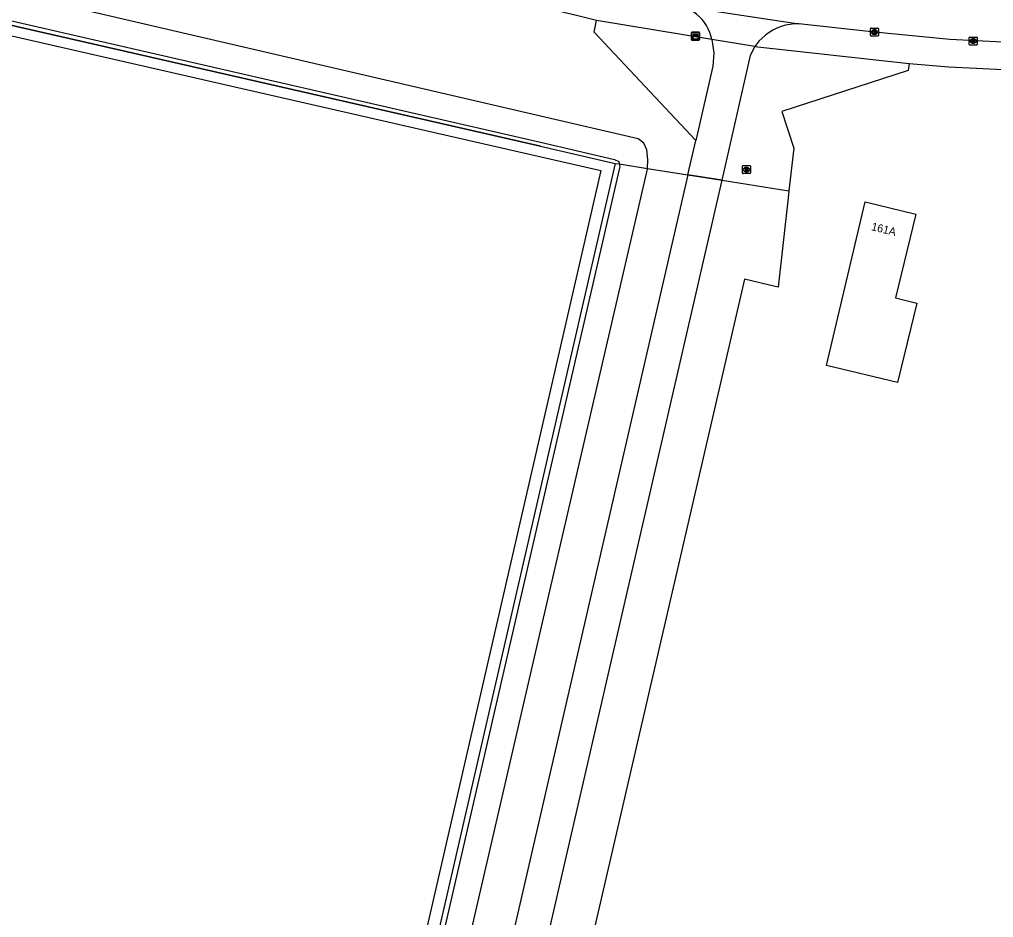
# Model space of a CAD drawing. Extents: x 160203 to 161526, y 379529 to 381797.
# Drawn here: x 160934.9 to 161056.6, y 381615.5 to 381727.7 of the extents above; entities that cross this region are included whole.
import ezdxf

# ---------------------------------------------------------------- set-up
doc = ezdxf.new("R2010")
doc.units = 0
for name, color, linetype in [('IMGEO_Fietspad_gesloten', 7, 'Continuous'), ('IMGEO_Groenvoorziening', 7, 'Continuous'), ('IMGEO_Hek', 7, 'Continuous'), ('IMGEO_Kast', 7, 'Continuous'), ('IMGEO_Kolk', 7, 'Continuous'), ('IMGEO_Loofbos', 7, 'Continuous'), ('IMGEO_Pand', 7, 'Continuous'), ('IMGEO_Pand_nummerreeks', 7, 'Continuous'), ('IMGEO_Rijbaan_lokaal_gesloten', 7, 'Continuous'), ('IMGEO_Rijbaan_lokaal_open', 7, 'Continuous'), ('IMGEO_Rioolput', 7, 'Continuous'), ('IMGEO_Voetpad_open', 7, 'Continuous'), ('IMGEO_Waterloop', 7, 'Continuous')]:
    doc.layers.add(name, color=color, linetype=linetype)

msp = doc.modelspace()

# ---------------------------------------------------------------- linework, layer by layer
at = {"layer": 'IMGEO_Fietspad_gesloten'}
msp.add_lwpolyline([(161059.6, 381724.82), (161059.22, 381724.83), (161057.74, 381724.86), (161051.18, 381725.22), (161049.02, 381725.4), (161041.76, 381726.12), (161032.31, 381727.14)], dxfattribs=at)
at = {"layer": 'IMGEO_Groenvoorziening'}
for points in [[(160905.47, 381607.79), (160932.99, 381725.88), (161007.56, 381708.83), (160982.28, 381598.99), (160979.33, 381590.62)], [(161046.1, 381722.18), (161045.95, 381721.32), (161030.18, 381716.2), (161031.67, 381711.63), (161031.06, 381706.3)], [(161022.69, 381707.62), (161031.06, 381706.3)], [(161031.06, 381706.3), (161030.96, 381705.4), (161029.69, 381694.26), (161028.46, 381694.55), (161025.49, 381695.25), (161006.56, 381613.31), (161001.18, 381614.12)]]:
    msp.add_lwpolyline(points, dxfattribs=at)
at = {"layer": 'IMGEO_Hek'}
for points in [[(161000, 381711.85), (160931.91, 381727.39)], [(161000, 381711.85), (161009.35, 381709.72)], [(161009.35, 381709.72), (161000, 381669.16)], [(161009.35, 381709.72), (161009.85, 381709.64)], [(161009.85, 381709.64), (161013.36, 381709.08)], [(161013.36, 381709.08), (161018.41, 381708.29)], [(161018.41, 381708.29), (161022.69, 381707.62)], [(161022.69, 381707.62), (161031.06, 381706.3)], [(161000, 381669.16), (160982.41, 381592.73), (160991.3, 381590.54)]]:
    msp.add_lwpolyline(points, dxfattribs=at)
at = {"layer": 'IMGEO_Kast'}
for p, q in [((161018.95, 381726.11), (161019.79, 381726.11)), ((161019.79, 381726.11), (161018.95, 381726.11)), ((161018.87, 381725.18), (161018.87, 381726.02)), ((161018.87, 381726.02), (161018.87, 381725.18)), ((161019.8, 381725.11), (161018.96, 381725.11)), ((161018.96, 381725.11), (161019.8, 381725.11)), ((161019.87, 381726.03), (161019.87, 381725.19)), ((161019.87, 381725.19), (161019.87, 381726.03))]:
    msp.add_line(p, q, dxfattribs=at)
for points in [[(161019.07, 381725.9), (161019.67, 381725.9), (161019.67, 381725.81), (161019.07, 381725.81), (161019.07, 381725.9)], [(161019.07, 381725.72), (161019.67, 381725.72), (161019.67, 381725.24), (161019.07, 381725.24), (161019.07, 381725.72)]]:
    msp.add_lwpolyline(points, dxfattribs=at)
msp.add_circle((161019.15, 381725.57), 0.0377, dxfattribs=at)
for centre, start, end in [((161018.95, 381726.03), 92.4484, 184.2845), ((161018.95, 381726.03), 92.4484, 184.2845), ((161019.79, 381726.03), 2.4484, 94.2845), ((161019.79, 381726.03), 2.4484, 94.2845), ((161018.95, 381725.19), 182.4484, 274.2845), ((161018.95, 381725.19), 182.4484, 274.2845), ((161019.79, 381725.19), 272.4484, 4.2845), ((161019.79, 381725.19), 272.4484, 4.2845)]:
    msp.add_arc(centre, 0.0779, start, end, dxfattribs=at)
at = {"layer": 'IMGEO_Kolk'}
for p, q in [((161041.24, 381725.69), (161041.24, 381726.55)), ((161041.32, 381726.62), (161042.17, 381726.62)), ((161041.73, 381726.4), (161041.75, 381726.4)), ((161042.24, 381726.55), (161042.24, 381725.69)), ((161042.17, 381725.62), (161041.32, 381725.62)), ((161041.75, 381725.84), (161041.73, 381725.84)), ((161053.6, 381724.58), (161053.6, 381725.44)), ((161053.67, 381725.51), (161054.52, 381725.51)), ((161054.08, 381725.29), (161054.11, 381725.29)), ((161054.6, 381725.44), (161054.6, 381724.58)), ((161054.52, 381724.51), (161053.67, 381724.51)), ((161054.11, 381724.73), (161054.08, 381724.73))]:
    msp.add_line(p, q, dxfattribs=at)
for points in [[(161041.24, 381725.69), (161041.24, 381726.55)], [(161041.32, 381726.62), (161042.17, 381726.62)], [(161041.56, 381726.32), (161041.69, 381726.32), (161041.69, 381726.17), (161041.81, 381726.32), (161041.98, 381726.32), (161041.83, 381726.17), (161041.99, 381725.92), (161041.83, 381725.92), (161041.75, 381726.09), (161041.69, 381726.02), (161041.69, 381725.92), (161041.56, 381725.92), (161041.56, 381726.32)], [(161042.24, 381726.55), (161042.24, 381725.69)], [(161042.17, 381725.62), (161041.32, 381725.62)], [(161053.6, 381724.58), (161053.6, 381725.44)], [(161053.67, 381725.51), (161054.52, 381725.51)], [(161053.92, 381725.21), (161054.04, 381725.21), (161054.04, 381725.06), (161054.17, 381725.21), (161054.33, 381725.21), (161054.19, 381725.06), (161054.34, 381724.81), (161054.19, 381724.81), (161054.1, 381724.98), (161054.04, 381724.91), (161054.04, 381724.81), (161053.92, 381724.81), (161053.92, 381725.21)], [(161054.6, 381725.44), (161054.6, 381724.58)], [(161054.52, 381724.51), (161053.67, 381724.51)]]:
    msp.add_lwpolyline(points, dxfattribs=at)
for centre, start, end in [((161041.32, 381726.55), 91.552, 178.448), ((161041.32, 381726.55), 91.552, 178.448), ((161042.17, 381726.55), 1.552, 88.448), ((161042.17, 381726.55), 1.552, 88.448), ((161041.32, 381725.7), 181.552, 268.448), ((161041.32, 381725.7), 181.552, 268.448), ((161042.17, 381725.7), 271.552, 358.448), ((161042.17, 381725.7), 271.552, 358.448), ((161053.67, 381725.44), 91.552, 178.448), ((161053.67, 381725.44), 91.552, 178.448), ((161054.52, 381725.44), 1.552, 88.448), ((161054.52, 381725.44), 1.552, 88.448), ((161053.67, 381724.59), 181.552, 268.448), ((161053.67, 381724.59), 181.552, 268.448), ((161054.52, 381724.59), 271.552, 358.448), ((161054.52, 381724.59), 271.552, 358.448)]:
    msp.add_arc(centre, 0.0765, start, end, dxfattribs=at)
for centre, major_axis, ratio, start_param, end_param in [((161041.73, 381726.12), (-0.387, 0.002), 0.722429, 4.712389, 7.853982), ((161041.75, 381726.12), (-0.39, 0.002), 0.717154, 1.570796, 4.712389), ((161054.08, 381725.01), (-0.387, 0.002), 0.722429, 4.712389, 7.853982), ((161054.11, 381725.01), (-0.39, 0.002), 0.717154, 1.570796, 4.712389)]:
    msp.add_ellipse(centre, major_axis=major_axis, ratio=ratio, start_param=start_param, end_param=end_param, dxfattribs=at)
at = {"layer": 'IMGEO_Loofbos'}
for points in [[(160885.25, 381510.67), (160899.54, 381573.29), (160879.8, 381577.74), (160888.45, 381614.64), (160904.95, 381610.88), (160911.88, 381640.18), (160931.91, 381727.39), (161000, 381711.85), (161009.35, 381709.72)], [(161019.4, 381712.56), (161006.69, 381726.12), (161006.98, 381727.59)], [(161009.35, 381709.72), (161000, 381669.16), (160982.41, 381592.73), (160991.3, 381590.54)], [(161009.35, 381709.72), (161009.85, 381709.64)], [(161013.36, 381709.08), (161018.41, 381708.29)]]:
    msp.add_lwpolyline(points, dxfattribs=at)
at = {"layer": 'IMGEO_Pand'}
msp.add_lwpolyline([(161044.63, 381682.32), (161035.76, 381684.47), (161040.57, 381704.93), (161046.74, 381703.43), (161046.9, 381703.39), (161044.36, 381692.91), (161047.04, 381692.26), (161044.63, 381682.32)], dxfattribs=at)
at = {"layer": 'IMGEO_Rijbaan_lokaal_gesloten'}
for points in [[(161021.4, 381725.18), (161021.68, 381723.53), (161021.55, 381721.86), (161019.4, 381712.56)], [(161026.81, 381724.32), (161021.4, 381725.18)], [(161022.69, 381707.62), (161026.27, 381723.21), (161026.81, 381724.32)], [(161018.41, 381708.29), (161019.4, 381712.56)], [(161018.41, 381708.29), (161000, 381628.33), (160991.3, 381590.54)], [(161022.69, 381707.62), (161018.41, 381708.29)], [(161001.18, 381614.12), (161022.69, 381707.62)]]:
    msp.add_lwpolyline(points, dxfattribs=at)
at = {"layer": 'IMGEO_Rijbaan_lokaal_open'}
for points in [[(161017.12, 381729.45), (161032.31, 381727.14)], [(161021.4, 381725.18), (161021.3, 381725.64), (161021.15, 381726.09), (161020.97, 381726.53), (161020.74, 381726.94), (161020.49, 381727.34), (161020.19, 381727.71), (161019.87, 381728.05), (161019.51, 381728.36), (161019.13, 381728.64), (161018.73, 381728.89), (161018.3, 381729.09), (161017.86, 381729.26), (161017.4, 381729.39), (161017.12, 381729.45)], [(161032.31, 381727.14), (161031.75, 381727.14), (161031.19, 381727.09), (161030.63, 381726.98), (161030.09, 381726.83), (161029.56, 381726.63), (161029.06, 381726.38), (161028.58, 381726.09), (161028.12, 381725.76), (161027.7, 381725.38), (161027.31, 381724.98), (161026.96, 381724.53), (161026.81, 381724.32)]]:
    msp.add_lwpolyline(points, dxfattribs=at)
at = {"layer": 'IMGEO_Rioolput'}
for p, q in [((161025.25, 381708.52), (161025.25, 381709.37)), ((161025.32, 381709.44), (161026.18, 381709.44)), ((161025.74, 381709.22), (161025.76, 381709.22)), ((161026.25, 381709.37), (161026.25, 381708.52)), ((161026.18, 381708.44), (161025.32, 381708.44)), ((161025.76, 381708.66), (161025.73, 381708.66))]:
    msp.add_line(p, q, dxfattribs=at)
for points in [[(161025.25, 381708.52), (161025.25, 381709.37)], [(161025.32, 381709.44), (161026.18, 381709.44)], [(161025.84, 381709.14), (161025.58, 381709.14), (161025.58, 381708.74)], [(161025.76, 381709.06), (161025.71, 381709.06), (161025.71, 381708.98)], [(161026.25, 381709.37), (161026.25, 381708.52)], [(161026.18, 381708.44), (161025.32, 381708.44)], [(161025.58, 381708.74), (161025.71, 381708.74), (161025.71, 381708.9), (161025.72, 381708.9)], [(161025.71, 381708.98), (161025.76, 381708.98)], [(161025.77, 381708.87), (161025.84, 381708.74), (161025.98, 381708.74), (161025.91, 381708.87)]]:
    msp.add_lwpolyline(points, dxfattribs=at)
for centre, radius, start, end in [((161025.32, 381709.37), 0.0765, 91.552, 178.448), ((161025.32, 381709.37), 0.0765, 91.552, 178.448), ((161025.77, 381708.96), 0.0964, 77.0061, 93.1865), ((161025.78, 381709.02), 0.0378, 276.6634, 79.6772), ((161025.84, 381709.03), 0.109, 350.3612, 89.416), ((161026.17, 381709.37), 0.0765, 1.552, 88.448), ((161026.17, 381709.37), 0.0765, 1.552, 88.448), ((161025.32, 381708.52), 0.0765, 181.552, 268.448), ((161025.32, 381708.52), 0.0765, 181.552, 268.448), ((161025.72, 381708.85), 0.0533, 26.0293, 88.6989), ((161025.75, 381709.17), 0.19, 274.7715, 282.9687), ((161025.83, 381709.03), 0.112, 277.5842, 350.9817), ((161025.82, 381708.81), 0.108, 29.5134, 73.7905), ((161026.17, 381708.52), 0.0765, 271.552, 358.448), ((161026.17, 381708.52), 0.0765, 271.552, 358.448)]:
    msp.add_arc(centre, radius, start, end, dxfattribs=at)
for centre, major_axis, ratio, start_param, end_param in [((161025.74, 381708.94), (-0.387, 0.002), 0.722429, 4.712389, 7.853982), ((161025.76, 381708.94), (-0.39, 0.002), 0.717154, 1.570796, 4.712389)]:
    msp.add_ellipse(centre, major_axis=major_axis, ratio=ratio, start_param=start_param, end_param=end_param, dxfattribs=at)
at = {"layer": 'IMGEO_Voetpad_open'}
for points in [[(161006.98, 381727.59), (161004.83, 381728.11), (161003.1, 381728.54), (161000, 381729.31), (160986.83, 381732.59), (160971.62, 381736.75), (160928.46, 381749.42)], [(161021.4, 381725.18), (161006.98, 381727.59)], [(161026.81, 381724.32), (161046.1, 381722.18)], [(161046.1, 381722.18), (161051.03, 381721.77), (161062.09, 381721.23), (161073.95, 381720.37)]]:
    msp.add_lwpolyline(points, dxfattribs=at)
at = {"layer": 'IMGEO_Waterloop'}
for points in [[(161013.36, 381709.08), (161013.43, 381710.21), (161013.3, 381711.43), (161012.91, 381712.23), (161012.2, 381712.77), (161000, 381715.61), (160925.18, 381733.04), (160924.8, 381731.34), (160924.43, 381729.71), (160932.06, 381727.96), (161000, 381712.35), (161009.24, 381710.22), (161009.8, 381709.94), (161009.85, 381709.64)], [(161009.85, 381709.64), (161009.91, 381709.33), (161000, 381666.23), (160983.27, 381593.49), (160986.49, 381592.82), (161000, 381651.24), (161013.36, 381708.99), (161013.36, 381709.08)]]:
    msp.add_lwpolyline(points, dxfattribs=at)

# ---------------------------------------------------------------- texts
at = {"layer": 'IMGEO_Pand_nummerreeks'}
msp.add_text('161A', height=1, rotation=346.3733, dxfattribs=at).set_placement((161041.28, 381701.38))

doc.saveas('drawing.dxf')
